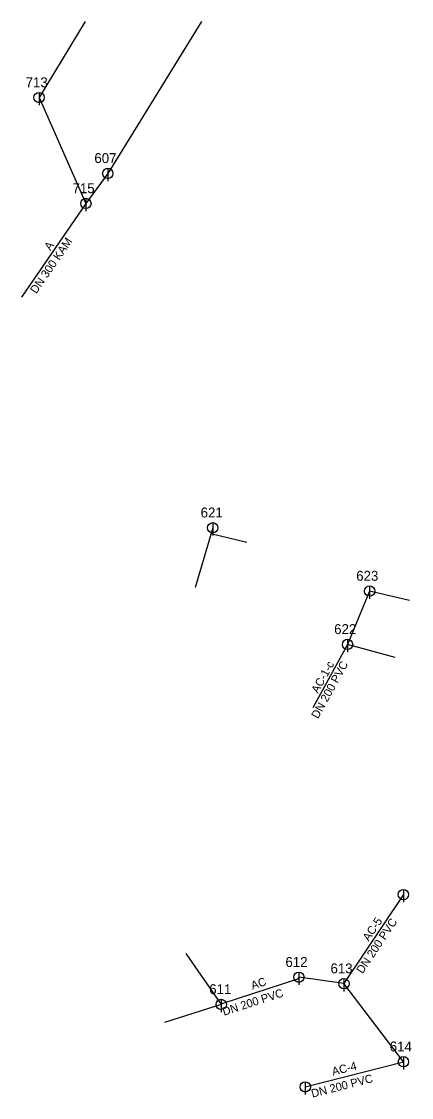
# Model space of a CAD drawing. Extents: x -557432 to -557356, y -1071812 to -1071603.
import ezdxf

# ---------------------------------------------------------------- set-up
doc = ezdxf.new("R2010")
doc.units = 0
for name, color, linetype in [('_pripojka_kanal_splaskova_priblizne_', 7, 'Continuous'), ('_stoka_splaskova_provozovana_prevzato_z_dokumentace_', 7, 'Continuous'), ('Default', 7, 'Continuous'), ('MoLevel 119', 7, 'Continuous'), ('MoLevel 120', 7, 'Continuous'), ('MoLevel 84', 7, 'Continuous'), ('MoLevel 85', 7, 'Continuous')]:
    doc.layers.add(name, color=color, linetype=linetype)

# ---------------------------------------------------------------- blocks, each defined once
blk = doc.blocks.new('_sachta_kanal_prevzato_z_dokumentace_')
at = {"layer": 'Default'}
blk.add_line((0, 0.00005), (0, -0.000075), dxfattribs=at)
blk.add_circle((0, 0), 0.00005, dxfattribs=at)

msp = doc.modelspace()

# ---------------------------------------------------------------- linework, layer by layer
at = {"layer": '_pripojka_kanal_splaskova_priblizne_'}
for p, q in [((-557387.87, -1071703.78), (-557394.82, -1071702.05)), ((-557356.23, -1071715.05), (-557363.97, -1071713.2)), ((-557359.02, -1071726.13), (-557368.26, -1071723.56))]:
    msp.add_line(p, q, dxfattribs=at)
at = {"layer": '_stoka_splaskova_provozovana_prevzato_z_dokumentace_'}
for p, q in [((-557419.25, -1071602.54), (-557428.23, -1071617.31)), ((-557396.64, -1071602.54), (-557414.87, -1071632.04)), ((-557428.23, -1071617.31), (-557419.12, -1071637.89)), ((-557414.87, -1071632.04), (-557419.12, -1071637.89)), ((-557419.12, -1071637.89), (-557431.64, -1071656.09)), ((-557394.48, -1071700.9), (-557397.88, -1071712.52)), ((-557363.97, -1071713.2), (-557368.26, -1071723.56)), ((-557368.26, -1071723.56), (-557375.04, -1071735.88)), ((-557357.42, -1071772.18), (-557368.97, -1071789.48)), ((-557399.72, -1071783.59), (-557392.81, -1071793.52)), ((-557368.97, -1071789.48), (-557377.73, -1071788.23)), ((-557357.4, -1071804.65), (-557368.97, -1071789.48)), ((-557392.81, -1071793.52), (-557403.87, -1071797.06)), ((-557376.48, -1071809.54), (-557357.4, -1071804.65))]:
    msp.add_line(p, q, dxfattribs=at)
msp.add_lwpolyline([(-557377.73, -1071788.23), (-557377.97, -1071788.6), (-557392.54, -1071793.33), (-557392.81, -1071793.52)], dxfattribs=at)

# ---------------------------------------------------------------- block references
at = {"layer": 'MoLevel 119', "xscale": 20000, "yscale": 20000}
for p in [(-557428.23, -1071617.31), (-557414.87, -1071632.04), (-557419.12, -1071637.89), (-557394.48, -1071700.9), (-557363.97, -1071713.2), (-557368.26, -1071723.56), (-557357.42, -1071772.18), (-557377.73, -1071788.23), (-557368.97, -1071789.48), (-557392.81, -1071793.52), (-557357.4, -1071804.65), (-557376.48, -1071809.54)]:
    msp.add_blockref('_sachta_kanal_prevzato_z_dokumentace_', p, dxfattribs=at)

# ---------------------------------------------------------------- texts
at = {"layer": 'MoLevel 120'}
for s, p in [('713', (-557430.84, -1071615.31)), ('607', (-557417.48, -1071630.04)), ('715', (-557421.73, -1071635.89)), ('621', (-557396.82, -1071698.9)), ('623', (-557366.58, -1071711.2)), ('622', (-557370.87, -1071721.56)), ('612', (-557380.34, -1071786.23)), ('613', (-557371.58, -1071787.48)), ('611', (-557395.15, -1071791.52)), ('614', (-557360.06, -1071802.65))]:
    msp.add_text(s, height=1.926, dxfattribs=at).set_placement(p)
at = {"layer": 'MoLevel 84'}
for s, rotation, p in [('DN 300 KAM', 55.4755, (-557428.77, -1071655.55)), ('DN 200 PVC', 61.1749, (-557374.01, -1071738.13)), ('DN 200 PVC', 56.2717, (-557365.35, -1071787.67)), ('DN 200 PVC', 17.9855, (-557392.28, -1071795.73)), ('DN 200 PVC', 14.3749, (-557375.1, -1071811.64))]:
    msp.add_text(s, height=1.605, rotation=rotation, dxfattribs=at).set_placement(p)
at = {"layer": 'MoLevel 85'}
for s, height, rotation, p in [('A', 1.6, 55.4755, (-557426.04, -1071647.15)), ('AC-1-c', 1.605, 61.1749, (-557374.01, -1071733.21)), ('AC-5', 1.605, 56.2717, (-557364.13, -1071781.37)), ('AC', 1.605, 17.9855, (-557386.75, -1071790.65)), ('AC-4', 1.605, 14.3749, (-557371.09, -1071807.36))]:
    msp.add_text(s, height=height, rotation=rotation, dxfattribs=at).set_placement(p)

doc.saveas('drawing.dxf')
